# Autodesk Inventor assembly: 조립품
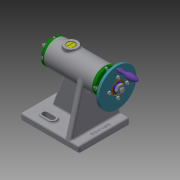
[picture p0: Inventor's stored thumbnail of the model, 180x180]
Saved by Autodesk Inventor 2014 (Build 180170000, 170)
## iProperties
Created: 2019-10
Part Number: 조립품
Document SubType Name: Assembly
Designer: kh
Author: kh
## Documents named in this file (18)
- C:\Users\kh\Desktop\491004V1002\조립품.iam
- C:\Users\kh\Desktop\491004V1002\본체.ipt
- C:\Users\kh\Desktop\491004V1002\공용부품\나사.ipt
- C:\Users\kh\Desktop\491004V1002\공용부품\나사축.ipt
- C:\Users\kh\Desktop\491004V1002\공용부품\너트 M8.ipt
- C:\Users\kh\Desktop\491004V1002\공용부품\돌림판.ipt
- C:\Users\kh\Desktop\491004V1002\공용부품\멈춤나사 M3.ipt
- C:\Users\kh\Desktop\491004V1002\공용부품\볼트 M3.ipt
- C:\Users\kh\Desktop\491004V1002\공용부품\부시.ipt
- C:\Users\kh\Desktop\491004V1002\공용부품\센터.ipt
- C:\Users\kh\Desktop\491004V1002\공용부품\센터홀더.ipt
- C:\Users\kh\Desktop\491004V1002\공용부품\슬리브.ipt
- C:\Users\kh\Desktop\491004V1002\공용부품\와셔.ipt
- C:\Users\kh\Desktop\491004V1002\공용부품\중공축.ipt
- C:\Users\kh\Desktop\491004V1002\공용부품\커버.ipt
- C:\Users\kh\Desktop\491004V1002\공용부품\키 4 x 4 x 10.ipt
- C:\Users\kh\Desktop\491004V1002\공용부품\플랜지.ipt
- C:\Users\kh\Desktop\491004V1002\공용부품\핸들.ipt
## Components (2 placed, 2 different names)
1. 플랜지:1 — Insert:4, Mate:1, Insert:9, Insert:10, Insert:17
2. 핸들:1 — Mate:2, Flush:1
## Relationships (7: Insert 4, Mate 2, Flush 1)
- Insert:4: 플랜지:1
- Mate:1: 플랜지:1
- Insert:9: 플랜지:1
- Insert:10: 플랜지:1
- Mate:2: 핸들:1
- Flush:1: 핸들:1
- Insert:17: 플랜지:1
